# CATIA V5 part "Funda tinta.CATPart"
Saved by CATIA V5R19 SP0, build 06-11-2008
Material "Grey": density 7860 kg/m3, Young's modulus 2e+11 Pa, Poisson ratio 0.266
Bounding box of the stored display mesh (mm): x -1.6 to 1.6, y -2.35 to 2.35, z -96 to 0
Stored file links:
  D:\TR\libro\ejemplo\terminados\BOLIGRAFO\Funda tinta.CATPart
  D:\TR\libro\ejemplo\terminados\BOLIGRAFO\Grupo boligrafo.CATProduct
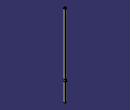
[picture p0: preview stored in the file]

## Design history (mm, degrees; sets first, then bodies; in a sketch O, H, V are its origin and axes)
AxisSystem1: origin (0, 0, 0), X (1, 0, 0), Y (0, 1, 0), Z (0, 0, 1)
Body1 "PartBody" (main body)
  Sketch1 on yz-plane, origin (0, 0, 0), H (0, 1, 0), V (0, 0, 1)
    line L1 (0, 0) -> (1.6, 0)
    line L2 (1.6, 0) -> (1.6, -72)
    point P3 (1.3, -74.5)
    line L3 (1.5515, -74.5) -> (1.6, -74.5)
    point P4 (1.6, -74.5)
    line L4 (1.6, -74.5) -> (1.6, -96)
    line L5 (1.6, -96) -> (0, -96)
    point P6 (0, -96)
    arc A1 centre (-8.9667, -72) radius 10.5667 from (1.6, -72) to (1.3561, -74.2573) cw
    point P8 (1.3, -74.5)
    arc A2 centre (1.5515, -74.3) radius 0.2 from (1.5515, -74.5) to (1.3561, -74.2573) cw
    construction line L6 (1.3, -74.5) -> (1.5515, -74.5)
    construction arc A3 centre (-8.9667, -72) radius 10.5667 from (1.3561, -74.2573) to (1.3, -74.5) cw
    axis line L7 (0, 8.3699) -> (0, -107.6981)
    point P13 (0, 8.3699)
    distance L2 V = 1.6
    distance H L5 = 96
    length L4 = 21.5
    length L2 = 72
    distance P3 P4 = 0.3
    radius A2 = 0.2
    horizontal: L1 H, L3 H, L5 H
    vertical: L2 V, L4 V, L7 V
    coincidence: P4 L2, P6 V, P8 P3, L3 P3, A1 P8, L3 L6, A1 A3, P13 V
    tangency: A1 L2, A2 L3, A2 A1
  Shaft1: profile Sketch1, axis Sketch1.L7, angle 360
  Sketch2 on yz-plane, origin (0, 0, 0), H (0, 1, 0), V (0, 0, 1)
    reference projected line E1 (1.6, -74.5) -> (-1.6, -74.5) from edge [face of Shaft1 from Sketch1.L3 | face of Shaft1 from Sketch1.L4]
    reference projected line E2 (1.6, -72) -> (-1.6, -72) from edge [face of Shaft1 from Sketch1.L2 | face of Shaft1 from Sketch1.A1]
    point P3 (1.6, -72)
    point P4 (-1.6, -72)
    point P5 (2.35, -74.5)
    line L1 (2.35, -74.5) -> (2.35, -74.017)
    point P6 (2.35, -74.017)
    arc A1 centre (1.35, -74.017) radius 1 from (2.35, -74.017) to (2.1692, -73.4434) ccw
    point P8 (2.1692, -73.4434)
    line L2 (2.1692, -73.4434) -> (1.9617, -73.1472)
    point P9 (1.9617, -73.1472)
    arc A2 centre (3.6, -72) radius 2 from (1.9617, -73.1472) to (1.6, -72) cw
    point P11 (1.6, -72)
    construction line L3 (1.6, -72) -> (1.6, -71.6485)
    point P13 (-2.35, -74.017)
    point P14 (-2.35, -74.5)
    line L4 (-2.35, -74.5) -> (-2.35, -74.017)
    point P15 (-2.1692, -73.4434)
    arc A3 centre (-1.35, -74.017) radius 1 from (-2.35, -74.017) to (-2.1692, -73.4434) cw
    point P17 (-1.9617, -73.1472)
    line L5 (-2.1692, -73.4434) -> (-1.9617, -73.1472)
    point P18 (-1.6, -72)
    arc A4 centre (-3.6, -72) radius 2 from (-1.9617, -73.1472) to (-1.6, -72) ccw
    line L6 (-1.6, -72) -> (1.6, -72)
    line L7 (-2.35, -74.5) -> (2.35, -74.5)
    distance L1 V = 2.35
    radius A2 = 2
    radius A1 = 1
    angle L2 E1 = 55
    coincidence: P5 E1, P11 P3, P4 P18
    tangency: A1 L1, L2 A1, A2 L2, L3 A2
    vertical: L1 V
    perpendicularity: L3 E2
    symmetry: P6 P13 V, P5 P14 V, L1 L4 V, P8 P15 V, A1 A3 V, P9 P17 V, L2 L5 V, P11 P18 V, A2 A4 V
    horizontal: L6 H, L7 H
  Pad1: profile Sketch2, direction (1, 0, 0), length 0.15, mirrored extent
  Sketch3 on face of Shaft1 from Sketch1.L5, origin (0, 0, -96), H (1, 0, 0), V (0, -1, 0)
    point P1 (0, 0)
  Hole1: placed by Sketch3, at (0, 0, -96) direction (0, 0, 1), diameter 2, through (limit type 3)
